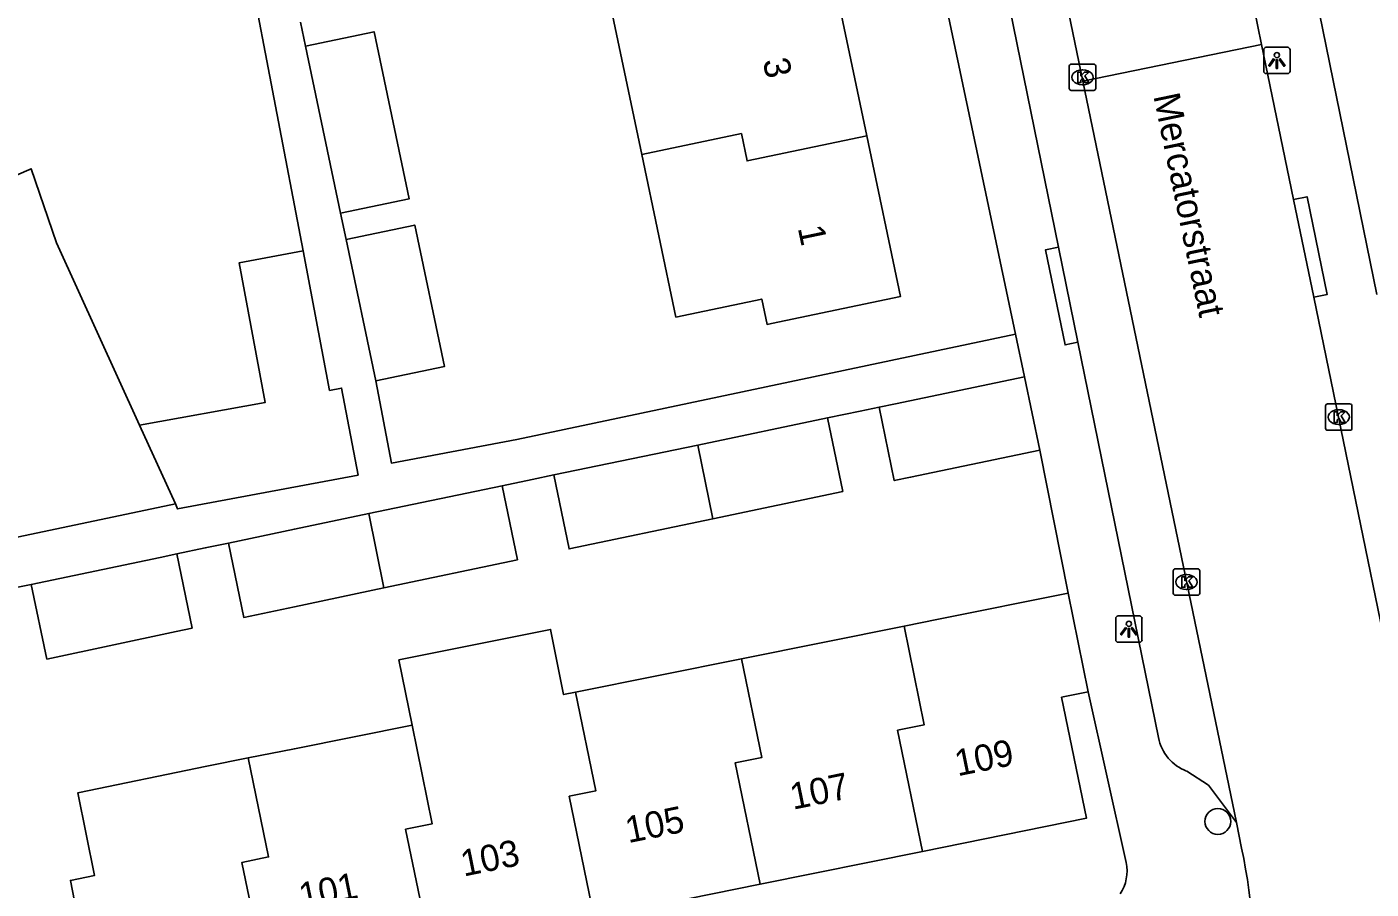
# Model space of a CAD drawing. Extents: x 162990 to 165007, y 383433 to 384336.
# Drawn here: x 163989.9 to 164040.8, y 384096 to 384128.7 of the extents above; entities that cross this region are included whole.
import ezdxf

# ---------------------------------------------------------------- set-up
doc = ezdxf.new("R2010")
doc.units = 0
for name, color, linetype in [('IMGEO_Boom', 7, 'Continuous'), ('IMGEO_Kolk', 7, 'Continuous'), ('IMGEO_Lichtpunt', 7, 'Continuous'), ('IMGEO_Openbare_ruimte_label', 7, 'Continuous'), ('IMGEO_Pand', 7, 'Continuous'), ('IMGEO_Pand_nummerreeks', 7, 'Continuous'), ('IMGEO_Rijbaan_lokaal_open', 7, 'Continuous'), ('IMGEO_Voetpad_open', 7, 'Continuous')]:
    doc.layers.add(name, color=color, linetype=linetype)

msp = doc.modelspace()

# ---------------------------------------------------------------- linework, layer by layer
at = {"layer": 'IMGEO_Boom'}
msp.add_circle((164034.983, 384098.612), 0.489, dxfattribs=at)
at = {"layer": 'IMGEO_Kolk'}
for p, q in [((164029.355, 384126.387), (164029.355, 384127.239)), ((164029.43, 384127.313), (164030.282, 384127.313)), ((164030.356, 384127.239), (164030.356, 384126.387)), ((164029.843, 384127.093), (164029.868, 384127.093)), ((164030.282, 384126.313), (164029.43, 384126.313)), ((164029.866, 384126.533), (164029.841, 384126.533)), ((164039.064, 384113.51), (164039.064, 384114.362)), ((164039.139, 384114.436), (164039.991, 384114.436)), ((164039.552, 384114.216), (164039.577, 384114.216)), ((164040.065, 384114.362), (164040.065, 384113.51)), ((164039.575, 384113.656), (164039.55, 384113.656)), ((164039.991, 384113.436), (164039.139, 384113.436)), ((164033.295, 384107.259), (164033.295, 384108.111)), ((164033.37, 384108.185), (164034.222, 384108.185)), ((164033.783, 384107.965), (164033.808, 384107.965)), ((164034.296, 384108.111), (164034.296, 384107.259)), ((164033.806, 384107.405), (164033.781, 384107.405)), ((164034.222, 384107.185), (164033.37, 384107.185))]:
    msp.add_line(p, q, dxfattribs=at)
for points in [[(164029.355, 384126.387), (164029.355, 384127.239)], [(164029.43, 384127.313), (164030.282, 384127.313)], [(164030.356, 384127.239), (164030.356, 384126.387)], [(164029.676, 384127.013), (164029.799, 384127.013), (164029.799, 384126.862), (164029.929, 384127.013), (164030.093, 384127.013), (164029.947, 384126.862), (164030.1, 384126.613), (164029.948, 384126.613), (164029.863, 384126.777), (164029.799, 384126.71), (164029.799, 384126.613), (164029.676, 384126.613), (164029.676, 384127.013)], [(164030.282, 384126.313), (164029.43, 384126.313)], [(164039.064, 384113.51), (164039.064, 384114.362)], [(164039.139, 384114.436), (164039.991, 384114.436)], [(164039.385, 384114.136), (164039.508, 384114.136), (164039.508, 384113.985), (164039.638, 384114.136), (164039.802, 384114.136), (164039.656, 384113.985), (164039.809, 384113.736), (164039.657, 384113.736), (164039.572, 384113.9), (164039.508, 384113.833), (164039.508, 384113.736), (164039.385, 384113.736), (164039.385, 384114.136)], [(164040.065, 384114.362), (164040.065, 384113.51)], [(164039.991, 384113.436), (164039.139, 384113.436)], [(164033.295, 384107.259), (164033.295, 384108.111)], [(164033.37, 384108.185), (164034.222, 384108.185)], [(164033.616, 384107.885), (164033.739, 384107.885), (164033.739, 384107.734), (164033.869, 384107.885), (164034.033, 384107.885), (164033.887, 384107.734), (164034.04, 384107.485), (164033.888, 384107.485), (164033.803, 384107.649), (164033.739, 384107.582), (164033.739, 384107.485), (164033.616, 384107.485), (164033.616, 384107.885)], [(164034.296, 384108.111), (164034.296, 384107.259)], [(164034.222, 384107.185), (164033.37, 384107.185)]]:
    msp.add_lwpolyline(points, dxfattribs=at)
for centre, start, end in [((164029.432, 384127.237), 91.552, 178.448), ((164029.432, 384127.237), 91.552, 178.448), ((164030.28, 384127.237), 1.552, 88.448), ((164030.28, 384127.237), 1.552, 88.448), ((164029.432, 384126.389), 181.552, 268.448), ((164029.432, 384126.389), 181.552, 268.448), ((164030.28, 384126.389), 271.552, 358.448), ((164030.28, 384126.389), 271.552, 358.448), ((164039.141, 384114.36), 91.552, 178.448), ((164039.141, 384114.36), 91.552, 178.448), ((164039.989, 384114.36), 1.552, 88.448), ((164039.989, 384114.36), 1.552, 88.448), ((164039.141, 384113.512), 181.552, 268.448), ((164039.141, 384113.512), 181.552, 268.448), ((164039.989, 384113.512), 271.552, 358.448), ((164039.989, 384113.512), 271.552, 358.448), ((164033.372, 384108.109), 91.552, 178.448), ((164033.372, 384108.109), 91.552, 178.448), ((164034.22, 384108.109), 1.552, 88.448), ((164034.22, 384108.109), 1.552, 88.448), ((164033.372, 384107.261), 181.552, 268.448), ((164033.372, 384107.261), 181.552, 268.448), ((164034.22, 384107.261), 271.552, 358.448), ((164034.22, 384107.261), 271.552, 358.448)]:
    msp.add_arc(centre, 0.0765, start, end, dxfattribs=at)
for centre, major_axis, ratio, start_param, end_param in [((164029.842, 384126.813), (-0.387, 0.002), 0.722429, 4.712389, 7.853982), ((164029.867, 384126.813), (-0.39, 0.002), 0.717154, 1.570796, 4.712389), ((164039.551, 384113.936), (-0.387, 0.002), 0.722429, 4.712389, 7.853982), ((164039.576, 384113.936), (-0.39, 0.002), 0.717154, 1.570796, 4.712389), ((164033.782, 384107.685), (-0.387, 0.002), 0.722429, 4.712389, 7.853982), ((164033.807, 384107.685), (-0.39, 0.002), 0.717154, 1.570796, 4.712389)]:
    msp.add_ellipse(centre, major_axis=major_axis, ratio=ratio, start_param=start_param, end_param=end_param, dxfattribs=at)
at = {"layer": 'IMGEO_Lichtpunt'}
for p, q in [((164036.723, 384127.855), (164036.723, 384127.048)), ((164036.723, 384127.855), (164036.723, 384127.048)), ((164037.625, 384127.95), (164036.817, 384127.95)), ((164037.625, 384127.95), (164036.817, 384127.95)), ((164037.719, 384127.048), (164037.719, 384127.855)), ((164037.719, 384127.048), (164037.719, 384127.855)), ((164036.817, 384126.954), (164037.625, 384126.954)), ((164036.817, 384126.954), (164037.625, 384126.954)), ((164032.016, 384106.399), (164031.208, 384106.399)), ((164032.016, 384106.399), (164031.208, 384106.399)), ((164031.114, 384106.304), (164031.114, 384105.497)), ((164031.114, 384106.304), (164031.114, 384105.497)), ((164032.11, 384105.497), (164032.11, 384106.304)), ((164032.11, 384105.497), (164032.11, 384106.304)), ((164031.208, 384105.403), (164032.016, 384105.403)), ((164031.208, 384105.403), (164032.016, 384105.403))]:
    msp.add_line(p, q, dxfattribs=at)
for points in [[(164037.097, 384127.519), (164037.136, 384127.491), (164036.948, 384127.229), (164036.91, 384127.256), (164037.097, 384127.519)], [(164037.199, 384127.471), (164037.246, 384127.471), (164037.246, 384127.149), (164037.199, 384127.149), (164037.199, 384127.471)], [(164037.309, 384127.491), (164037.347, 384127.518), (164037.534, 384127.256), (164037.495, 384127.228), (164037.309, 384127.491)], [(164031.488, 384105.968), (164031.527, 384105.94), (164031.339, 384105.678), (164031.301, 384105.705), (164031.488, 384105.968)], [(164031.59, 384105.92), (164031.637, 384105.92), (164031.637, 384105.598), (164031.59, 384105.598), (164031.59, 384105.92)], [(164031.7, 384105.94), (164031.738, 384105.967), (164031.925, 384105.705), (164031.886, 384105.677), (164031.7, 384105.94)]]:
    msp.add_lwpolyline(points, dxfattribs=at)
for centre in [(164037.222, 384127.653), (164031.613, 384106.102)]:
    msp.add_circle(centre, 0.0994, dxfattribs=at)
for centre, start, end in [((164036.817, 384127.855), 90, 180), ((164036.817, 384127.855), 90, 180), ((164037.625, 384127.855), 0, 90), ((164037.625, 384127.855), 0, 90), ((164036.817, 384127.048), 180, 270), ((164036.817, 384127.048), 180, 270), ((164037.625, 384127.048), 270, 0), ((164037.625, 384127.048), 270, 360), ((164031.208, 384106.304), 90, 180), ((164031.208, 384106.304), 90, 180), ((164032.016, 384106.304), 0, 90), ((164032.016, 384106.304), 0, 90), ((164031.208, 384105.497), 180, 270), ((164031.208, 384105.497), 180, 270), ((164032.016, 384105.497), 270, 0), ((164032.016, 384105.497), 270, 360)]:
    msp.add_arc(centre, 0.0946, start, end, dxfattribs=at)
at = {"layer": 'IMGEO_Pand'}
for points in [[(164021.685, 384124.597), (164020.322, 384131.09)], [(164011.798, 384130.38), (164013.161, 384123.887)], [(164001.747, 384121.664), (164004.35, 384122.212), (164003.019, 384128.541), (164000.415, 384127.995)], [(164000.415, 384127.995), (164001.747, 384121.664)], [(164013.161, 384123.887), (164016.932, 384124.677), (164017.147, 384123.642), (164021.685, 384124.597)], [(164021.685, 384124.597), (164022.963, 384118.507), (164018.07, 384117.48), (164017.907, 384117.446), (164017.705, 384118.409), (164014.454, 384117.726), (164013.161, 384123.887)], [(163983.777, 384115.329), (163987.765, 384117.106), (163987.136, 384118.607), (163985.624, 384121.452), (163990.019, 384123.347), (163990.979, 384120.541), (163994.13, 384113.636)], [(164003.084, 384115.309), (164005.687, 384115.856), (164004.56, 384121.214), (164001.957, 384120.666)], [(164001.957, 384120.666), (164003.084, 384115.309)], [(164000.335, 384120.235), (163997.899, 384119.777), (163998.894, 384114.491), (163994.13, 384113.636)], [(163995.492, 384110.651), (163995.571, 384110.454), (164002.408, 384111.74), (164001.788, 384115.035), (164001.33, 384114.949), (164000.335, 384120.235)], [(164027.664, 384115.46), (164022.77, 384114.44), (164022.155, 384114.312)], [(164027.664, 384115.46), (164028.236, 384112.681)], [(164022.155, 384114.312), (164022.725, 384111.527), (164023.343, 384111.656), (164028.236, 384112.681)], [(163994.13, 384113.636), (163995.492, 384110.651)], [(164020.197, 384113.903), (164015.281, 384112.878)], [(164015.852, 384110.082), (164020.771, 384111.116), (164020.197, 384113.903)], [(164015.281, 384112.878), (164009.83, 384111.742)], [(164015.281, 384112.878), (164015.852, 384110.082)], [(164015.852, 384110.082), (164010.407, 384108.938), (164009.83, 384111.742)], [(164007.872, 384111.334), (164002.816, 384110.279)], [(164007.872, 384111.334), (164008.45, 384108.527), (164003.392, 384107.464)], [(163995.492, 384110.651), (163986.671, 384108.791)], [(164002.816, 384110.279), (164000, 384109.692), (163997.497, 384109.164)], [(164003.392, 384107.464), (164002.816, 384110.279)], [(164003.392, 384107.464), (164000, 384106.751), (163998.077, 384106.347), (163997.497, 384109.164)], [(163995.54, 384108.751), (163994.917, 384108.62), (163990.024, 384107.588)], [(163995.54, 384108.751), (163996.119, 384105.937), (163995.514, 384105.808), (163990.619, 384104.764), (163990.024, 384107.588)], [(164029.308, 384107.264), (164024.406, 384106.281), (164023.095, 384106.014)], [(164029.308, 384107.264), (164030.077, 384103.527)], [(164010.653, 384103.51), (164010.198, 384103.418), (164009.701, 384105.889), (164003.959, 384104.734), (164004.456, 384102.263)], [(164023.095, 384106.014), (164016.938, 384104.775)], [(164023.797, 384097.479), (164022.85, 384102.069), (164023.86, 384102.274), (164023.095, 384106.014)], [(164016.938, 384104.775), (164010.653, 384103.51)], [(164017.642, 384096.23), (164016.693, 384100.83), (164017.703, 384101.035), (164016.938, 384104.775)], [(164011.359, 384094.954), (164010.408, 384099.565), (164011.418, 384099.77), (164010.653, 384103.51)], [(164023.797, 384097.479), (164030.008, 384098.74), (164029.066, 384103.318), (164030.077, 384103.527)], [(164004.456, 384102.263), (164000, 384101.37), (163998.25, 384101.018)], [(164004.456, 384102.263), (164005.221, 384098.523), (164004.211, 384098.318), (164005.165, 384093.696)], [(163998.25, 384101.018), (163996.684, 384100.703), (163991.787, 384099.691), (163992.423, 384096.563), (163991.511, 384096.377), (163991.669, 384095.597), (163992.575, 384091.141), (163998.962, 384092.437)], [(163998.962, 384092.437), (163998.008, 384097.06), (163999.018, 384097.265), (163998.25, 384101.018)], [(164017.642, 384096.23), (164023.797, 384097.479)], [(164011.359, 384094.954), (164017.642, 384096.23)]]:
    msp.add_lwpolyline(points, dxfattribs=at)
at = {"layer": 'IMGEO_Rijbaan_lokaal_open'}
for points in [[(164035.66, 384132.841), (164036.643, 384128.061)], [(164028.886, 384131.44), (164029.875, 384126.661)], [(164036.643, 384128.061), (164029.875, 384126.661)], [(164037.853, 384122.18), (164036.643, 384128.061)], [(164029.875, 384126.661), (164035.685, 384098.569)], [(164038.615, 384118.477), (164037.853, 384122.18)], [(164043.001, 384097.155), (164038.615, 384118.477)], [(164035.885, 384097.602), (164035.685, 384098.569)]]:
    msp.add_lwpolyline(points, dxfattribs=at)
msp.add_arc((164012.046, 384092.662), 24.346, 341.4455, 11.7072, dxfattribs=at)
at = {"layer": 'IMGEO_Voetpad_open'}
for points in [[(164041.007, 384118.587), (164037.434, 384136.117), (164036.135, 384142.418), (164034.043, 384152.9)], [(164020.594, 384148.951), (164027.323, 384117.074)], [(164028.948, 384120.376), (164024.487, 384142.259)], [(163997.183, 384136.7), (164000.335, 384120.235)], [(164000.415, 384127.995), (164000.224, 384128.906)], [(164037.853, 384122.18), (164038.366, 384122.285), (164039.125, 384118.581), (164038.615, 384118.477)], [(164001.957, 384120.666), (164001.747, 384121.664)], [(164029.683, 384116.774), (164029.194, 384116.674), (164028.459, 384120.276), (164028.948, 384120.376)], [(164029.683, 384116.774), (164028.948, 384120.376)], [(164027.323, 384117.074), (164008.419, 384113.083), (164003.671, 384112.19), (164003.084, 384115.309)], [(164027.323, 384117.074), (164027.664, 384115.46)], [(164032.737, 384101.791), (164029.683, 384116.774)], [(164022.155, 384114.312), (164021.429, 384114.16), (164020.197, 384113.903)], [(164028.236, 384112.681), (164029.308, 384107.264)], [(164009.83, 384111.742), (164009.004, 384111.57), (164007.872, 384111.334)], [(163997.497, 384109.164), (163996.621, 384108.979), (163995.54, 384108.751)], [(163990.024, 384107.588), (163986.047, 384106.81)], [(164030.077, 384103.527), (164031.509, 384097.056)], [(164035.685, 384098.569), (164034.628, 384099.987), (164033.803, 384100.521)]]:
    msp.add_lwpolyline(points, dxfattribs=at)
for centre, radius, start, end in [((164034.386, 384102.093), 1.677, 190.3722, 249.646), ((164029.968, 384096.727), 1.575, 326.8294, 12.0533)]:
    msp.add_arc(centre, radius, start, end, dxfattribs=at)

# ---------------------------------------------------------------- texts
at = {"layer": 'IMGEO_Openbare_ruimte_label'}
msp.add_text('Mercatorstraat', height=1, rotation=281.7706, dxfattribs=at).set_placement((164032.537, 384126.11))
at = {"layer": 'IMGEO_Pand_nummerreeks'}
for s, rotation, p in [('3', 281.8535, (164017.736, 384127.444)), ('1', 281.8535, (164019.066, 384121.105)), ('109', 11.4758, (164025.126, 384100.321)), ('107', 11.4758, (164018.887, 384099.054)), ('105', 11.4758, (164012.648, 384097.788)), ('103', 11.4763, (164006.409, 384096.521)), ('101', 11.4758, (164000.282, 384095.277))]:
    msp.add_text(s, height=1, rotation=rotation, dxfattribs=at).set_placement(p)

doc.saveas('drawing.dxf')
